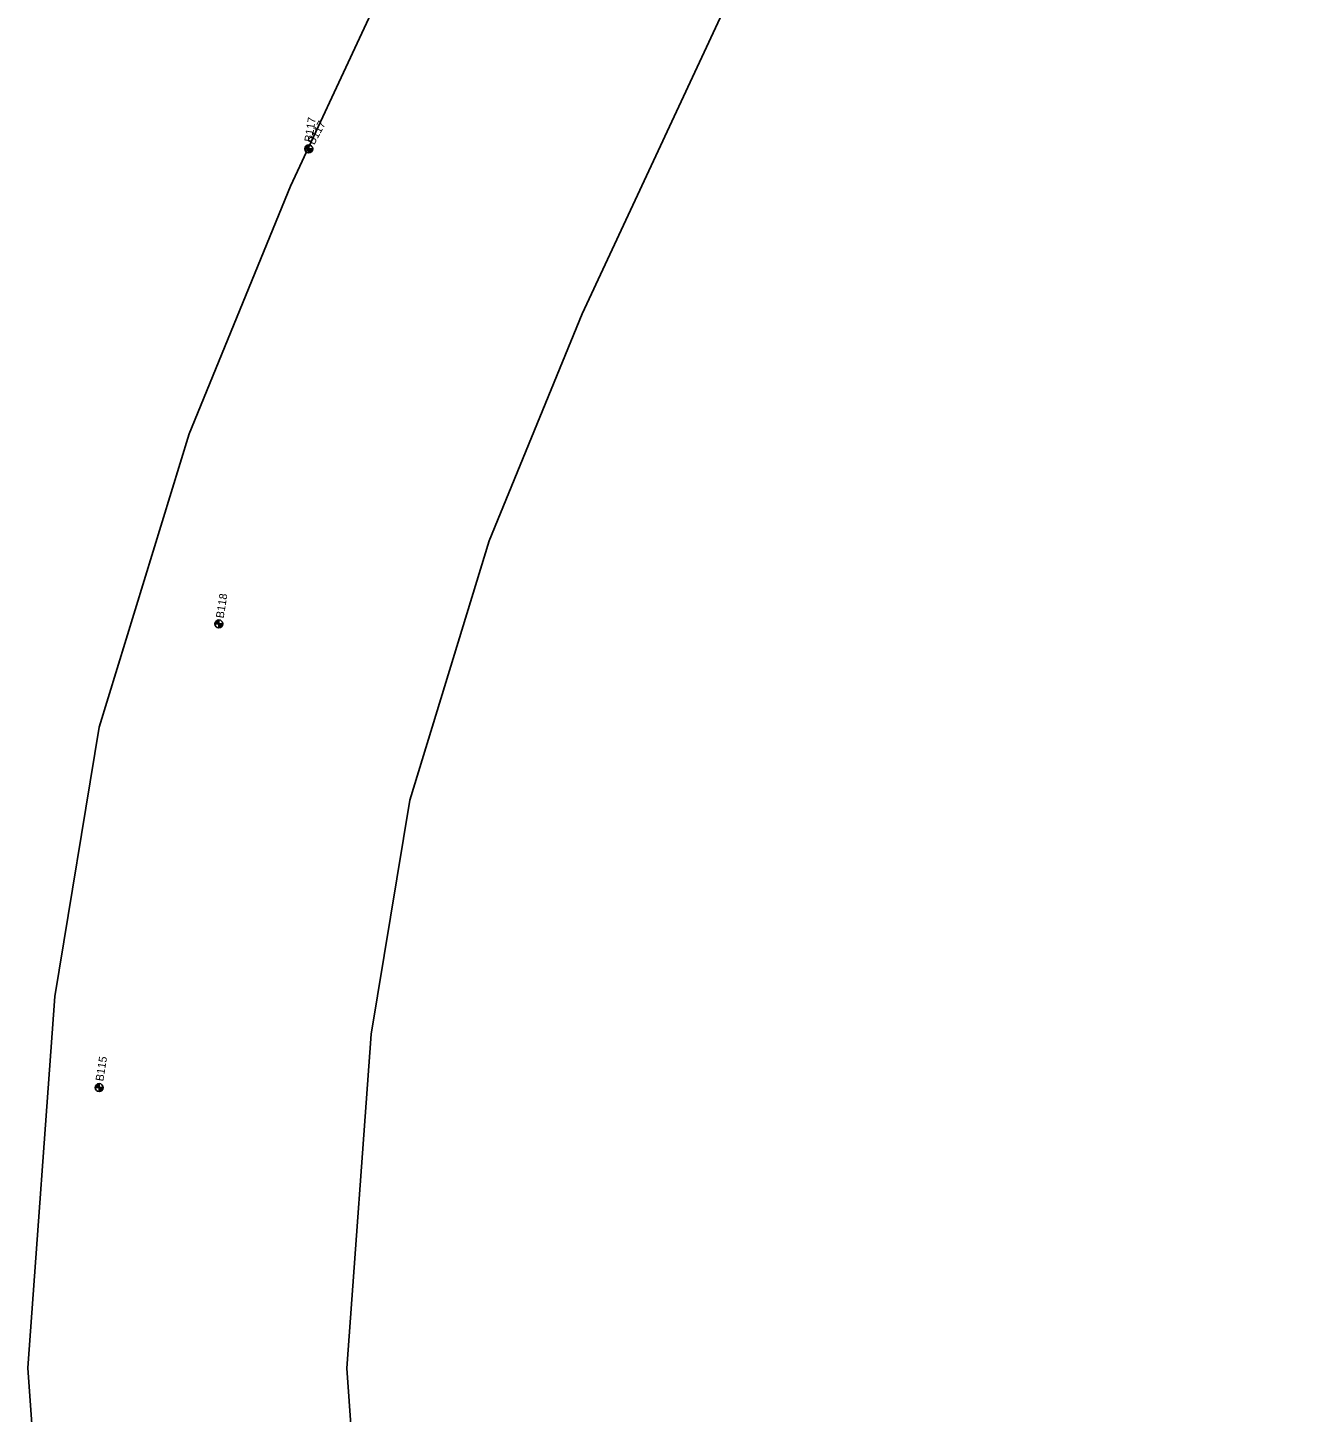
# Model space of a CAD drawing. Extents: x 327762 to 372792, y 127949 to 259367.
# Drawn here: x 355040 to 356660, y 192178 to 193918 of the extents above; entities that cross this region are included whole.
import ezdxf

# ---------------------------------------------------------------- set-up
doc = ezdxf.new("R2010")
doc.units = 0
for name, color, linetype in [('E_SOIL_BORE1 [KAPUR_CADDS_LEVELS]', 7, 'Continuous'), ('E_SOIL_BORE2 [KAPUR_CADDS_LEVELS]', 7, 'Continuous'), ('P_MARK', 7, 'Continuous'), ('P_TC', 7, 'Continuous')]:
    doc.layers.add(name, color=color, linetype=linetype)

msp = doc.modelspace()

# ---------------------------------------------------------------- linework, layer by layer
at = {"layer": 'P_MARK'}
for p, q in [((355388.6, 193765.9), (355398.6, 193765.9)), ((355393.6, 193770.9), (355393.6, 193760.9)), ((355280.6, 193173.8), (355280.6, 193163.8)), ((355275.6, 193168.8), (355285.6, 193168.8)), ((355125.2, 192585.9), (355135.2, 192585.9)), ((355130.2, 192590.9), (355130.2, 192580.9))]:
    msp.add_line(p, q, dxfattribs=at)
for centre in [(355393.6, 193765.9), (355280.6, 193168.8), (355130.2, 192585.9)]:
    msp.add_circle(centre, 5, dxfattribs=at)
for centre, radius, start, end in [((355393.6, 193765.9), 4.5, 89.9869, 179.9869), ((355393.6, 193765.9), 4, 89.9869, 179.9869), ((355393.6, 193765.9), 3.5, 89.9869, 179.9869), ((355393.6, 193765.9), 3, 89.9869, 179.9869), ((355393.6, 193765.9), 2.5, 89.9869, 179.9869), ((355393.6, 193765.9), 2, 89.9869, 179.9869), ((355393.6, 193765.9), 1.5, 89.9869, 179.9869), ((355393.6, 193765.9), 1, 89.9869, 179.9869), ((355393.6, 193765.9), 0.5, 89.9869, 179.9869), ((355393.6, 193765.9), 4.5, 269.9869, 359.9869), ((355393.6, 193765.9), 4, 269.9869, 359.9869), ((355393.6, 193765.9), 3.5, 269.9869, 359.9869), ((355393.6, 193765.9), 3, 269.9869, 359.9869), ((355393.6, 193765.9), 2.5, 269.9869, 359.9869), ((355393.6, 193765.9), 2, 269.9869, 359.9869), ((355393.6, 193765.9), 1.5, 269.9869, 359.9869), ((355393.6, 193765.9), 1, 269.9869, 359.9869), ((355393.6, 193765.9), 0.5, 269.9869, 359.9869), ((355280.6, 193168.8), 4.5, 89.9869, 179.9869), ((355280.6, 193168.8), 4, 89.9869, 179.9869), ((355280.6, 193168.8), 3.5, 89.9869, 179.9869), ((355280.6, 193168.8), 3, 89.9869, 179.9869), ((355280.6, 193168.8), 2.5, 89.9869, 179.9869), ((355280.6, 193168.8), 2, 89.9869, 179.9869), ((355280.6, 193168.8), 1.5, 89.9869, 179.9869), ((355280.6, 193168.8), 1, 89.9869, 179.9869), ((355280.6, 193168.8), 0.5, 89.9869, 179.9869), ((355280.6, 193168.8), 4.5, 269.9869, 359.9869), ((355280.6, 193168.8), 4, 269.9869, 359.9869), ((355280.6, 193168.8), 3.5, 269.9869, 359.9869), ((355280.6, 193168.8), 3, 269.9869, 359.9869), ((355280.6, 193168.8), 2.5, 269.9869, 359.9869), ((355280.6, 193168.8), 2, 269.9869, 359.9869), ((355280.6, 193168.8), 1.5, 269.9869, 359.9869), ((355280.6, 193168.8), 1, 269.9869, 359.9869), ((355280.6, 193168.8), 0.5, 269.9869, 359.9869), ((355130.2, 192585.9), 4.5, 89.9869, 179.9869), ((355130.2, 192585.9), 4, 89.9869, 179.9869), ((355130.2, 192585.9), 3.5, 89.9869, 179.9869), ((355130.2, 192585.9), 3, 89.9869, 179.9869), ((355130.2, 192585.9), 2.5, 89.9869, 179.9869), ((355130.2, 192585.9), 2, 89.9869, 179.9869), ((355130.2, 192585.9), 1.5, 89.9869, 179.9869), ((355130.2, 192585.9), 1, 89.9869, 179.9869), ((355130.2, 192585.9), 0.5, 89.9869, 179.9869), ((355130.2, 192585.9), 4.5, 269.9869, 359.9869), ((355130.2, 192585.9), 4, 269.9869, 359.9869), ((355130.2, 192585.9), 3.5, 269.9869, 359.9869), ((355130.2, 192585.9), 3, 269.9869, 359.9869), ((355130.2, 192585.9), 2.5, 269.9869, 359.9869), ((355130.2, 192585.9), 2, 269.9869, 359.9869), ((355130.2, 192585.9), 1.5, 269.9869, 359.9869), ((355130.2, 192585.9), 1, 269.9869, 359.9869), ((355130.2, 192585.9), 0.5, 269.9869, 359.9869)]:
    msp.add_arc(centre, radius, start, end, dxfattribs=at)
at = {"layer": 'P_TC'}
for points in [[(355283.6, 189224), (355274.3, 189348.2), (355249.7, 189692.4), (355212.6, 190196.5), (355174, 190629), (355143, 191045.2), (355065.1, 191886.3), (355040.4, 192233.4), (355074.6, 192700.4), (355130.4, 193038.8), (355243.3, 193407.8), (355370.8, 193719.1), (355556, 194116.5), (355747.6, 194472.4), (355922.8, 194827.6), (356106.3, 195206.2), (356289.3, 195658.8)], [(356660.1, 195508.9), (356472.1, 195043.8), (356282.2, 194652), (356103.2, 194289), (355913.6, 193937), (355737.4, 193558.7), (355620.5, 193273.2), (355520.7, 192947.3), (355472.2, 192653.1), (355441.4, 192233), (355463.8, 191918.9), (355541.6, 191078.5), (355572.6, 190661.6), (355611.3, 190229), (355648.6, 189721.3), (355673.2, 189377.4), (355691.8, 189129.9)]]:
    msp.add_lwpolyline(points, dxfattribs=at)

# ---------------------------------------------------------------- texts
at = {"layer": 'E_SOIL_BORE1 [KAPUR_CADDS_LEVELS]'}
for s, p in [('B117', (355397.8, 193774)), ('B118', (355286.6, 193175.3)), ('B115', (355135.3, 192593.3))]:
    msp.add_text(s, height=10, rotation=80.9358, dxfattribs=at).set_placement(p)
at = {"layer": 'E_SOIL_BORE2 [KAPUR_CADDS_LEVELS]'}
msp.add_text('B117', height=10, rotation=61.5935, dxfattribs=at).set_placement((355400.4, 193770.2))

doc.saveas('drawing.dxf')
